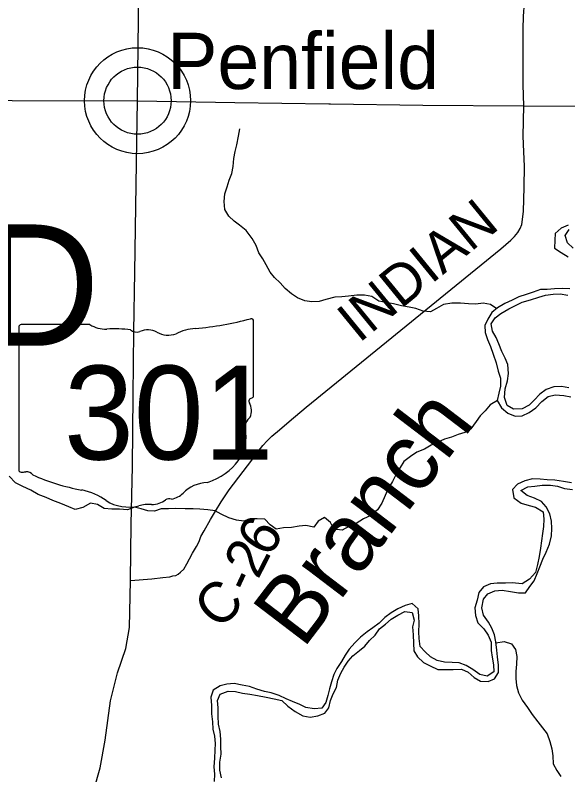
# Model space of a CAD drawing. Extents: x 1857828 to 2277390, y 930619 to 1324581.
# Drawn here: x 2071852 to 2075949, y 1149482 to 1155113 of the extents above; entities that cross this region are included whole.
import ezdxf

# ---------------------------------------------------------------- set-up
doc = ezdxf.new("R2010")
doc.units = 0
for name, color, linetype in [('GM_X_County_Road', 7, 'Continuous'), ('GM_X_County_Road_Text', 7, 'Continuous'), ('GM_X_Major_River', 7, 'Continuous'), ('GM_X_Major_River_Text', 7, 'Continuous'), ('GM_X_Minor_River', 7, 'Continuous'), ('GM_X_State_Location', 7, 'Continuous'), ('GM_X_State_Route', 7, 'Continuous'), ('GM_X_State_Shield', 7, 'Continuous'), ('GM_X_Township_Text', 7, 'Continuous'), ('GM_X_Unincorporated', 7, 'Continuous'), ('GM_X_Unincorporated_Location', 7, 'Continuous'), ('GM_X_Unincorporated_Text', 7, 'Continuous')]:
    doc.layers.add(name, color=color, linetype=linetype)

msp = doc.modelspace()

# ---------------------------------------------------------------- linework, layer by layer
at = {"layer": 'GM_X_County_Road'}
for points in [[(2075622.1, 1154440.5), (2075619.1, 1154596.7), (2075617.8, 1155010.4), (2075620.4, 1155106.7), (2075627, 1155205), (2075635.4, 1155263.2), (2075644, 1155337.4), (2075662.6, 1155425.6), (2075679.1, 1155491.8), (2075703.8, 1155575.9), (2075833.4, 1156038.7), (2076074.2, 1156922.3), (2076121.4, 1157074.5), (2076152.3, 1157196.8), (2076185.4, 1157351.1), (2076204.1, 1157435.3), (2076218.8, 1157543.6), (2076228, 1157714.2), (2076234.2, 1158055.4), (2076291.6, 1160425.8)], [(2072706.3, 1150922.1), (2072864.6, 1150935), (2072947.1, 1150944.4), (2072999.3, 1150950), (2073021.5, 1150955.9), (2073041.6, 1150959.7), (2073059.8, 1150969.6), (2073077.9, 1150983.6), (2073102.2, 1151005.5), (2073124.5, 1151045.4), (2073144.9, 1151083.5), (2073167.3, 1151125.5), (2073195.7, 1151175.4), (2073216, 1151211.4), (2073228.3, 1151249.5), (2073252.7, 1151291.5), (2073299.5, 1151373.5), (2073336, 1151435.4), (2073378.7, 1151505.3), (2073437.6, 1151593.3), (2073540.9, 1151729), (2073605.8, 1151814.9), (2073654.4, 1151878.8), (2073688.8, 1151922.7), (2073721.2, 1151958.6), (2073755.6, 1151992.4), (2073812.2, 1152040.2), (2073882.9, 1152099.9), (2074010.2, 1152207.4), (2075452.5, 1153381.2), (2075527.2, 1153444.9), (2075553.5, 1153472.8), (2075577.8, 1153500.7), (2075596.1, 1153530.7), (2075608.3, 1153560.7), (2075621, 1153657), (2075626.2, 1153837.7), (2075627.2, 1153994.3), (2075623.9, 1154100.7), (2075618.6, 1154215.2), (2075622.1, 1154440.5)]]:
    msp.add_lwpolyline(points, dxfattribs=at)
at = {"layer": 'GM_X_Major_River'}
for points in [[(2075951.2, 1153555.2), (2075899, 1153532.9), (2075854.9, 1153494.6), (2075853.2, 1153444.4), (2075851.4, 1153386.1), (2075899.9, 1153354.1), (2075952.4, 1153322.2)], [(2075988.3, 1153384.6), (2075945.8, 1153424.6), (2075929.4, 1153480.8), (2075959.4, 1153523.1)], [(2075963.6, 1153083.2), (2075911.3, 1153087), (2075850.9, 1153084.8), (2075796.6, 1153078.6), (2075746.4, 1153078.4), (2075692.1, 1153060.1), (2075639.9, 1153041.8), (2075585.7, 1153025.6), (2075537.5, 1153001.3), (2075481.3, 1152975), (2075429.1, 1152942.6), (2075385.1, 1152908.3), (2075355.1, 1152860), (2075335.2, 1152813.7), (2075335.5, 1152761.5), (2075353.9, 1152709.3), (2075376.3, 1152657.2), (2075396.7, 1152599), (2075419.1, 1152536.8), (2075433.5, 1152474.6), (2075449.9, 1152422.4), (2075450.2, 1152362.1), (2075438.3, 1152311.9), (2075426.5, 1152257.6), (2075457, 1152201.4), (2075505.5, 1152161.4), (2075559.9, 1152139.5), (2075610.2, 1152143.7), (2075662.4, 1152168), (2075712.5, 1152202.3), (2075756.5, 1152248.7), (2075802.6, 1152285), (2075854.9, 1152299.3), (2075919.3, 1152293.5), (2075971.6, 1152283.6)], [(2075957.2, 1152349.9), (2075902.8, 1152359.7), (2075844.5, 1152357.5), (2075788.3, 1152339.2), (2075742.2, 1152302.9), (2075700.1, 1152258.6), (2075662.1, 1152222.3), (2075609.9, 1152193.9), (2075547.6, 1152191.7), (2075499.2, 1152219.7), (2075478.7, 1152277.8), (2075484.5, 1152342.2), (2075502.3, 1152402.5), (2075510, 1152456.8), (2075505.7, 1152523), (2075485.3, 1152569.2), (2075460.9, 1152619.3), (2075438.5, 1152677.5), (2075418.2, 1152723.6), (2075391.8, 1152769.7), (2075381.5, 1152823.9), (2075409.4, 1152870.2), (2075453.5, 1152902.6), (2075511.7, 1152934.9), (2075561.8, 1152961.2), (2075612, 1152985.5), (2075672.3, 1153001.8), (2075734.6, 1153022.1), (2075782.8, 1153038.3), (2075841.1, 1153044.6), (2075891.4, 1153046.8), (2075949.8, 1153036.9)], [(2075976.8, 1151646.8), (2075916.4, 1151656.6), (2075852, 1151666.4), (2075795.6, 1151668.2), (2075743.3, 1151674.1), (2075687, 1151675.9), (2075630.7, 1151661.6), (2075576.5, 1151637.3), (2075538.5, 1151597), (2075548.8, 1151534.8), (2075603.4, 1151494.8), (2075661.8, 1151478.9), (2075710.1, 1151465), (2075766.6, 1151431.1), (2075770.9, 1151376.9), (2075769.2, 1151322.6), (2075761.4, 1151270.3), (2075753.6, 1151216.1), (2075745.9, 1151161.8), (2075736.1, 1151099.5), (2075724.3, 1151041.2), (2075708.5, 1150980.9), (2075664.5, 1150932.5), (2075610.4, 1150898.1), (2075537.9, 1150903.9), (2075487.6, 1150901.7), (2075425.3, 1150903.5), (2075375, 1150897.3), (2075324.8, 1150875)], [(2075722.7, 1150974.9), (2075742.5, 1151023.2), (2075764.4, 1151079.5), (2075788.3, 1151131.8), (2075814.1, 1151192.2), (2075827.9, 1151254.5), (2075829.6, 1151306.8), (2075829.4, 1151363), (2075817, 1151415.2), (2075788.6, 1151469.3), (2075754.2, 1151507.4), (2075701.8, 1151533.3), (2075647.3, 1151553.2), (2075600.9, 1151589.2), (2075653.1, 1151617.5), (2075705.3, 1151621.7), (2075759.6, 1151629.9), (2075820, 1151628.2), (2075872.3, 1151620.3), (2075924.7, 1151604.4), (2075985.1, 1151596.6)], [(2073382.4, 1149459.8), (2073370, 1149516), (2073369.7, 1149576.2), (2073379.5, 1149634.5), (2073377.2, 1149692.8), (2073376.9, 1149745), (2073372.6, 1149803.3), (2073360.3, 1149857.5), (2073355.9, 1149915.7), (2073355.6, 1149978), (2073351.3, 1150032.2), (2073371.2, 1150080.5), (2073431.5, 1150100.8), (2073485.8, 1150099), (2073538.2, 1150087.1), (2073590.5, 1150079.3), (2073648.9, 1150069.4), (2073713.3, 1150057.6), (2073771.8, 1150043.8), (2073828.1, 1150031.9), (2073872.6, 1149989.9), (2073927.1, 1149951.9), (2073983.6, 1149920), (2074038, 1149910.1), (2074096.3, 1149918.4), (2074146.5, 1149938.6), (2074176.5, 1149978.9), (2074190.3, 1150033.2), (2074210.2, 1150081.5), (2074234.1, 1150129.8), (2074243.9, 1150182.1), (2074265.7, 1150234.4), (2074291.7, 1150280.7), (2074319.6, 1150323), (2074355.6, 1150363.3), (2074403.7, 1150403.6), (2074443.8, 1150435.9), (2074479.8, 1150478.2), (2074519.8, 1150516.6), (2074553.8, 1150564.9), (2074597.9, 1150599.2), (2074639.9, 1150635.5), (2074688.1, 1150665.8), (2074740.3, 1150692.1), (2074794.6, 1150684.3), (2074809, 1150628.1), (2074797.2, 1150577.8), (2074801.5, 1150519.6), (2074805.8, 1150457.3), (2074808.1, 1150401.1), (2074834.5, 1150357), (2074878.9, 1150314.9), (2074929.4, 1150289), (2074985.8, 1150263.1), (2075038.2, 1150261.2), (2075098.5, 1150261.5), (2075160.9, 1150263.7), (2075211.3, 1150241.8), (2075253.7, 1150203.8), (2075302.1, 1150175.8), (2075358.5, 1150174), (2075404.7, 1150194.3), (2075434.6, 1150240.6), (2075436.3, 1150294.8), (2075428, 1150355.1), (2075423.7, 1150405.3), (2075415.4, 1150467.5), (2075405, 1150519.7), (2075386.7, 1150569.9), (2075360.3, 1150614), (2075323.8, 1150666.1), (2075311.5, 1150720.3), (2075323.2, 1150784.6), (2075357.3, 1150822.9), (2075407.4, 1150845.2), (2075463.7, 1150851.4), (2075524.2, 1150839.6), (2075582.5, 1150831.8), (2075634.8, 1150831.9), (2075666.8, 1150878.2), (2075700.8, 1150920.6), (2075722.7, 1150974.9)], [(2075324.8, 1150875), (2075288.8, 1150832.7), (2075277, 1150776.4), (2075259.2, 1150720.1), (2075265.5, 1150663.9), (2075281.9, 1150607.7), (2075326.4, 1150563.6), (2075358.8, 1150517.6), (2075381.2, 1150465.4), (2075381.5, 1150403.1), (2075387.8, 1150352.9), (2075398.1, 1150296.7), (2075400.4, 1150244.5), (2075352.3, 1150212.1), (2075295.9, 1150226), (2075245.4, 1150262), (2075194.9, 1150291.9), (2075144.5, 1150311.9), (2075092.2, 1150313.7), (2075035.9, 1150317.5), (2074979.5, 1150329.3), (2074931, 1150357.3), (2074890.6, 1150393.3), (2074854.2, 1150433.4), (2074847.9, 1150491.6), (2074845.6, 1150541.8), (2074847.3, 1150602.1), (2074845, 1150660.4), (2074838.7, 1150712.6), (2074796.3, 1150752.6), (2074744.1, 1150736.3), (2074689.9, 1150712), (2074639.7, 1150681.7), (2074593.6, 1150647.4), (2074551.6, 1150605.1), (2074503.5, 1150570.7), (2074461.4, 1150542.5), (2074411.3, 1150502.1), (2074369.2, 1150459.8), (2074329.2, 1150413.4), (2074297.2, 1150369.1), (2074271.3, 1150320.8), (2074235.4, 1150270.4), (2074213.5, 1150224.2), (2074197.6, 1150171.9), (2074181.8, 1150119.6), (2074170, 1150069.3), (2074156.2, 1150019), (2074126.2, 1149976.7), (2074067.9, 1149970.5), (2074007.5, 1149980.3), (2073961.1, 1150002.3), (2073908.7, 1150024.2), (2073860.3, 1150046.1), (2073807.8, 1150070), (2073749.4, 1150089.9), (2073699.1, 1150099.8), (2073644.6, 1150117.7), (2073588.2, 1150135.5), (2073533.8, 1150147.4), (2073475.4, 1150159.2), (2073421.1, 1150153), (2073370.9, 1150140.8), (2073320.8, 1150108.5), (2073302.9, 1150058.2), (2073307.3, 1149995.9), (2073307.6, 1149933.6), (2073313.9, 1149873.4), (2073316.2, 1149821.2), (2073328.5, 1149769), (2073334.8, 1149714.8), (2073333.1, 1149664.5), (2073329.3, 1149604.2), (2073325.6, 1149541.9), (2073329.9, 1149485.7), (2073328.2, 1149431.5)]]:
    msp.add_lwpolyline(points, dxfattribs=at)
at = {"layer": 'GM_X_Minor_River'}
for points in [[(2075422.2, 1152937.2), (2075376.7, 1152968.6), (2075322.3, 1152978.4), (2075266.1, 1152970.2), (2075211.7, 1152972), (2075153.3, 1152977.8), (2075089, 1152977.6), (2075028.7, 1152967.3), (2074976.5, 1152939), (2074930.4, 1152912.7), (2074876, 1152918.6), (2074823.6, 1152938.5), (2074773.2, 1152948.3), (2074716.9, 1152958.2), (2074656.4, 1152974), (2074602.1, 1152983.9), (2074547.7, 1152993.7), (2074497.2, 1153027.7), (2074440.8, 1153037.6), (2074384.5, 1153037.3), (2074324.2, 1153029.1), (2074273.9, 1153024.9), (2074221.6, 1153022.7), (2074155.3, 1153004.4), (2074105.1, 1152990.1), (2074050.8, 1152987.9), (2074000.4, 1152995.8), (2073946, 1153017.7), (2073901.6, 1153047.7), (2073853.1, 1153087.7), (2073816.7, 1153127.7), (2073774.3, 1153167.8), (2073741.9, 1153207.8), (2073711.4, 1153262), (2073687, 1153306.1), (2073658.6, 1153352.2), (2073638.3, 1153406.3), (2073609.8, 1153458.5), (2073565.3, 1153516.6), (2073514.8, 1153556.6), (2073474.4, 1153586.6), (2073436, 1153622.6), (2073405.6, 1153672.7), (2073401.2, 1153730.9), (2073407, 1153789.2), (2073422.8, 1153841.5), (2073438.7, 1153889.8), (2073458.6, 1153938.1), (2073468.3, 1153990.3), (2073472.1, 1154050.6), (2073481.9, 1154102.9), (2073495.7, 1154151.1), (2073507.5, 1154215.5), (2073517.2, 1154269.8)], [(2075426.9, 1152256.9), (2075374.4, 1152223.2), (2075336.4, 1152180.9), (2075298.3, 1152142.6), (2075270.4, 1152100.3), (2075230.4, 1152045.9), (2075186.3, 1152019.7), (2075136.1, 1152003.4), (2075087.9, 1151985.2), (2075035.7, 1151968.9), (2074985.5, 1151948.6), (2074935.3, 1151926.3), (2074887.2, 1151896), (2074830.9, 1151873.7), (2074782.8, 1151841.4), (2074732.7, 1151805.1), (2074706.8, 1151760.8), (2074676.8, 1151710.5), (2074648.9, 1151656.1), (2074617, 1151603.8), (2074595.1, 1151551.5), (2074571.3, 1151495.1), (2074537.3, 1151446.8), (2074489.2, 1151404.4), (2074435, 1151380.1), (2074380.9, 1151345.8), (2074324.7, 1151321.5), (2074276.5, 1151295.2), (2074214.1, 1151303), (2074189.7, 1151353.1), (2074145.3, 1151389.1), (2074099.1, 1151362.9), (2074067.2, 1151318.6), (2074006.8, 1151330.4), (2073956.5, 1151324.2), (2073900.2, 1151315.9), (2073841.9, 1151311.7), (2073787.6, 1151303.5), (2073741.2, 1151335.5), (2073702.7, 1151377.5), (2073646.4, 1151379.3), (2073594.1, 1151379.1), (2073545.9, 1151362.9), (2073493.5, 1151368.7), (2073435.1, 1151386.6), (2073378.6, 1151414.5), (2073334.2, 1151438.5), (2073279.9, 1151446.3), (2073221.5, 1151450.1), (2073171.2, 1151454), (2073112.9, 1151453.8), (2073040.4, 1151455.5), (2072988.1, 1151453.3), (2072933.8, 1151453.1), (2072885.6, 1151436.9), (2072835.3, 1151438.7), (2072784.9, 1151452.6), (2072736.6, 1151466.5), (2072684.4, 1151446.2), (2072626, 1151450), (2072567.7, 1151449.8), (2072511.3, 1151455.6), (2072460.9, 1151485.6), (2072410.5, 1151495.4), (2072352.3, 1151463.1), (2072296.1, 1151448.8), (2072249.7, 1151468.7), (2072189.2, 1151492.6), (2072130.8, 1151514.5), (2072080.4, 1151536.4), (2072021.9, 1151560.3), (2071967.4, 1151592.3), (2071908.9, 1151618.2), (2071854.5, 1151646.1), (2071806.9, 1151695.7)], [(2075416.2, 1150461.3), (2075477.7, 1150469.8), (2075532.1, 1150453.9), (2075560.5, 1150409.8), (2075570.8, 1150357.6), (2075569.1, 1150301.3), (2075563.3, 1150247.1), (2075563.6, 1150194.8), (2075569.9, 1150142.6), (2075584.2, 1150088.4), (2075610.7, 1150034.3), (2075651.2, 1149980.2), (2075685.6, 1149928.1), (2075726.1, 1149874), (2075760.6, 1149829.9), (2075795, 1149785.8), (2075815.4, 1149729.6), (2075829.7, 1149673.4), (2075838, 1149623.2), (2075840.4, 1149563), (2075866.8, 1149512.8), (2075897.2, 1149468.8)]]:
    msp.add_lwpolyline(points, dxfattribs=at)
at = {"layer": 'GM_X_State_Route'}
for points in [[(2072759, 1154479), (2072853.5, 1162123.8), (2072894.3, 1165427), (2072956.1, 1165629.1), (2072992.7, 1165838.3), (2073054.9, 1174012.4), (2073108.7, 1175839.2)], [(2070898, 1154483.3), (2072759, 1154479)], [(2072392.9, 1149219.1), (2072481.3, 1149534.1), (2072518.3, 1149738.9), (2072558.8, 1150030.1), (2072609.9, 1150237.1), (2072673.2, 1150418), (2072700.4, 1150572.6), (2072706.3, 1150922.1), (2072712.2, 1151339.3), (2072721.8, 1151766.7), (2072726.8, 1152292.5), (2072732.2, 1152768.1), (2072737.7, 1153207.6), (2072745, 1153695.3), (2072754.3, 1154176.9), (2072759, 1154479)], [(2072759, 1154479), (2073479.8, 1154465.4), (2074176.9, 1154456.9), (2074190.5, 1154456.7)], [(2074190.5, 1154456.7), (2074874, 1154446.3), (2075622.1, 1154440.5), (2076071.2, 1154438.2), (2076689.9, 1154435.3), (2077376.9, 1154430.6), (2078082, 1154428.1), (2078757, 1154423.4), (2079885.7, 1154410.6), (2080639.2, 1154406.7), (2081352.3, 1154400.2), (2082802.7, 1154389.3), (2083184.9, 1154387.7), (2083459.5, 1154386.6), (2084056.2, 1154379.5), (2084711, 1154376.8), (2085420.1, 1154370.3), (2086019, 1154363.1)]]:
    msp.add_lwpolyline(points, dxfattribs=at)
at = {"layer": 'GM_X_State_Shield'}
for p, q in [((2071878.8, 1152800.9), (2071878.8, 1151744.3)), ((2072405.5, 1152819.1), (2071895.9, 1152819.1)), ((2073619, 1152292.5), (2073619, 1152845.3)), ((2073618.8, 1152292.7), (2073619, 1152292.5))]:
    msp.add_line(p, q, dxfattribs=at)
for centre, major_axis, start_param, end_param in [((2072999.1, 1154259.6), (1845.5, 0), 4.814394, 5.042369), ((2073599.7, 1152847.5), (19.4, 0), 6.141152, 7.989035), ((2071898.7, 1152803.1), (20.2, 0), 1.712693, 3.28349), ((2072526.9, 1152941.7), (195.5, 0), 4.042523, 4.731795), ((2072591.7, 1152225.9), (702, 0), 1.404758, 1.657858), ((2072751.1, 1152808.6), (56.4, 0), 3.836095, 5.185415), ((2072833.9, 1152686.5), (117.3, 0), 0.950623, 2.079405), ((2072985.3, 1152854), (141.1, 0), 4.081561, 5.145723), ((2073234.5, 1152496.3), (371.3, 0), 1.699011, 2.107814), ((2073614.5, 1152251.9), (30, 0), 1.883978, 3.671073), ((2073423.8, 1152182.1), (180, 0), 5.934695, 6.695948), ((2073598.3, 1152290.4), (20.7, 0), 5.05454, 6.418171), ((2073688.4, 1152061.2), (130.9, 0), 2.387724, 3.262537), ((2073102.5, 1151990.9), (461.6, 0), 5.101752, 6.440018), ((2071898.9, 1151741.9), (20.3, 0), 3.00124, 4.508301), ((2071902, 1151850), (155.2, 0), 4.665946, 4.897461), ((2071933.7, 1151683.3), (56, 0), 0.519207, 1.627899), ((2072640.3, 1152632.6), (1332.7, 0), 4.195997, 4.488961), ((2073297.1, 1151447.6), (252.8, 0), 1.647645, 2.488434), ((2072243, 1151269.6), (417, 0), 0.823519, 1.323587), ((2072976.8, 1151641.8), (149.1, 0), 4.937069, 5.64225), ((2072694, 1151678.1), (264.6, 0), 4.026481, 4.996735), ((2072866.2, 1151598.9), (141, 0), 4.691044, 5.507374), ((2072993.7, 1151496.6), (39.7, 0), 1.147584, 2.315152), ((2072846.9, 1151312.7), (217.4, 0), 1.495662, 1.94098)]:
    msp.add_ellipse(centre, major_axis=major_axis, ratio=0.8, start_param=start_param, end_param=end_param, dxfattribs=at)
at = {"layer": 'GM_X_Unincorporated'}
for radius in [392.8, 249]:
    msp.add_circle((2072759, 1154479), radius, dxfattribs=at)
at = {"layer": 'GM_X_Unincorporated_Location'}
msp.add_line((2072759, 1154479), (2072759, 1154479), dxfattribs=at)

# ---------------------------------------------------------------- texts
at = {"layer": 'GM_X_County_Road_Text'}
for s, rotation, p in [('INDIAN', 39.2576, (2074400.6, 1152677.2)), ('6', 58.3758, (2073733.2, 1151083.4)), ('2', 63.0207, (2073652.5, 1150924.4)), ('-', 64.9276, (2073601.5, 1150815.1)), ('C', 44.9696, (2073361.9, 1150548))]:
    msp.add_text(s, height=300, rotation=rotation, dxfattribs=at).set_placement(p)
at = {"layer": 'GM_X_Major_River_Text'}
msp.add_text('Branch', height=500.26, rotation=52.6851, dxfattribs=at).set_placement((2073984.7, 1150406.7))
at = {"layer": 'GM_X_State_Location'}
for s in ['s', 'r']:
    msp.add_text(s, height=1, dxfattribs=at).set_placement((2072729.3, 1152202.3))
msp.add_text('301', height=1, rotation=0, dxfattribs=at).set_placement((2072376.3, 1152129.6))
at = {"layer": 'GM_X_State_Shield'}
msp.add_text('301', height=696.1, dxfattribs=at).set_placement((2072213.4, 1151818.8))
at = {"layer": 'GM_X_Township_Text'}
msp.add_text('PENFIELD', height=900, rotation=0, dxfattribs=at).set_placement((2066594.6, 1152662.1))
at = {"layer": 'GM_X_Unincorporated_Text'}
msp.add_text('Penfield', height=417, rotation=0, dxfattribs=at).set_placement((2072979.1, 1154565.4))

doc.saveas('drawing.dxf')
